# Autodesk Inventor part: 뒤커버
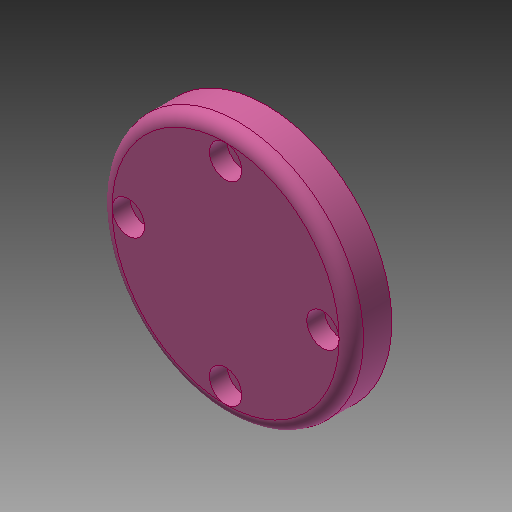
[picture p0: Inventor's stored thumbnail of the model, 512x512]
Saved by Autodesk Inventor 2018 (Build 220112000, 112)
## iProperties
Created: 2015-09
Part Number: 뒤커버
Material: 알루미늄 6061
Document SubType Name: Modeling
Designer: mduedu
Density: 1 g/cm^3
Appearance: 분홍색
Author: mduedu
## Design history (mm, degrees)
sketch "스케치1"
  geometry: L1 (0, 7.5)-(0, -7.5); L2 (0, 7.5)-(31, 7.5); L3 (31, 7.5)-(31, -2.5); L4 (31, -2.5)-(17.5, -2.5); L5 (17.5, -2.5)-(17.5, -7.5); L6 (17.5, -7.5)-(0, -7.5); 2 further points
  constraints: 12 end point, 2 parallel, 2 perpendicular, 1 coincident, 1 horizontal, 1 midpoint, 1 vertical
  dimensions: "d0" = 15 distance of L1.start L1.end; "d1" = 62 diameter of L3 L1; "d2" = 35 diameter of L5 L1; "d3" = 10 distance of L2.end L3.end
revolve "회전1" sketch "스케치1" stored, may be unused: angle "d4" = 90 deg
fillet "모깎기2" dims "d48" = 3
sketch "스케치4" dims "d49" = 48
  geometry: 3 further points
  constraints: 2 vertical alignment, 1 coincident, 2 other
hole "구멍4" sketch "스케치4" at (0, 24) diameter "d50" = 4.5; stored, may be unused: countersink angle "d54" = 90 deg, drill point angle "d56" = 118 deg; dims "d51" = 6, "d52" = 8, "d53" = 4.4, "d55" = 8
hole "구멍5" diameter "d62" = 24; stored, may be unused: countersink angle "d66" = 90 deg, drill point angle "d68" = 0 deg; dims "d60" = 10, "d61" = 10, "d63" = 6, "d64" = 4, "d65" = 2, "d67" = 8
fillet "모깎기3" dims "d69" = 3
chamfer "모따기3" distance "d43" = 1; stored, may be unused: second distance "d44" = 2, angle "d45" = 45 deg
node "솔리드1"
pattern_circular "원형 패턴1" dims angle "d58" = 360 deg
